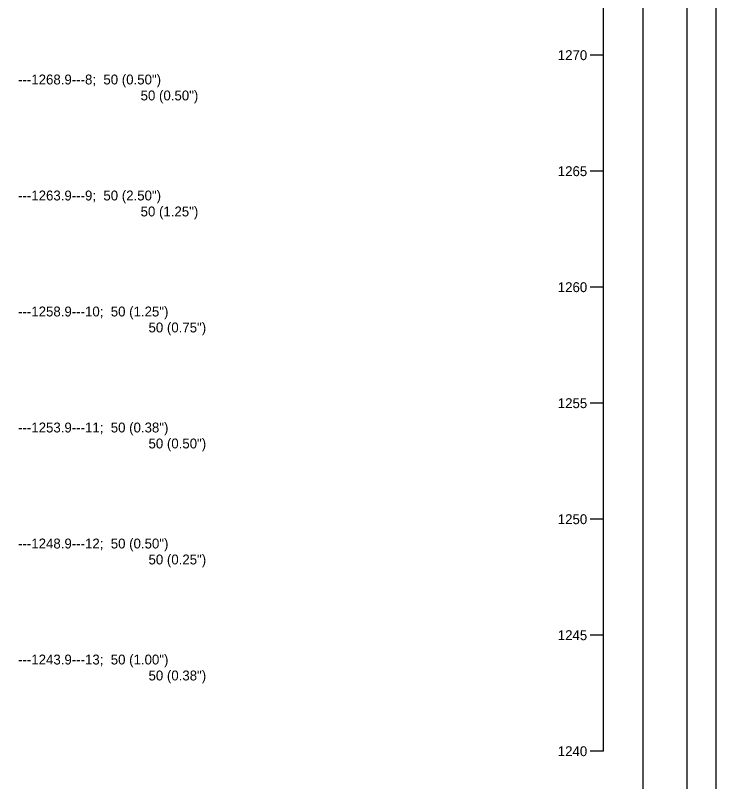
# Model space of a CAD drawing. Extents: x 7 to 126, y 24 to 56.
# Drawn here: x 33.85 to 42.62, y 36.64 to 46.24 of the extents above; entities that cross this region are included whole.
import ezdxf

# ---------------------------------------------------------------- set-up
doc = ezdxf.new("R2010")
doc.units = 0
for name, color, linetype in [('SHT_Plot_Shape_Full', 7, 'Continuous'), ('SHT_Plot_Shape_Half', 7, 'Continuous'), ('SHT_Sheet_Border', 7, 'Continuous')]:
    doc.layers.add(name, color=color, linetype=linetype)

msp = doc.modelspace()

# ---------------------------------------------------------------- linework, layer by layer
msp.add_line((41.2167, 37.0213), (41.2167, 50.1027))
for points in [[(41.2167, 45.7423), (41.05, 45.7423)], [(41.2167, 44.2888), (41.05, 44.2888)], [(41.2167, 42.8353), (41.05, 42.8353)], [(41.2167, 41.3818), (41.05, 41.3818)], [(41.2167, 39.9283), (41.05, 39.9283)], [(41.2167, 38.4748), (41.05, 38.4748)], [(41.2167, 37.0213), (41.05, 37.0213)]]:
    msp.add_lwpolyline(points)
at = {"layer": 'SHT_Plot_Shape_Full'}
msp.add_lwpolyline([(6.6242, 53.9713), (42.6243, 53.9713), (42.6243, 29.9713), (6.6242, 29.9713)], close=True, dxfattribs=at)
at = {"layer": 'SHT_Plot_Shape_Half'}
msp.add_lwpolyline([(8.2617, 53.1463), (42.2618, 53.1463), (42.2618, 31.1463), (8.2617, 31.1463)], close=True, dxfattribs=at)
at = {"layer": 'SHT_Sheet_Border'}
msp.add_lwpolyline([(10.2117, 52.6463), (41.7118, 52.6463), (41.7118, 31.6463), (10.2117, 31.6463)], close=True, dxfattribs=at)

# ---------------------------------------------------------------- texts
for s, p in [('1270', (40.6459, 45.6803)), ('---1268.9---8;  50 (0.50")', (33.8836, 45.3754)), ('50 (0.50")', (35.4189, 45.1754)), ('1265', (40.6459, 44.2268)), ('---1263.9---9;  50 (2.50")', (33.8836, 43.922)), ('50 (1.25")', (35.4189, 43.722)), ('1260', (40.6459, 42.7733)), ('---1258.9---10;  50 (1.25")', (33.8836, 42.4685)), ('50 (0.75")', (35.5179, 42.2685)), ('1255', (40.6459, 41.3198)), ('---1253.9---11;  50 (0.38")', (33.8836, 41.015)), ('50 (0.50")', (35.5179, 40.815)), ('1250', (40.6459, 39.8663)), ('---1248.9---12;  50 (0.50")', (33.8836, 39.5615)), ('50 (0.25")', (35.5179, 39.3615)), ('1245', (40.6459, 38.4128)), ('---1243.9---13;  50 (1.00")', (33.8836, 38.108)), ('50 (0.38")', (35.5179, 37.908)), ('1240', (40.6459, 36.9593))]:
    msp.add_text(s, height=0.124).set_placement(p)

doc.saveas('drawing.dxf')
